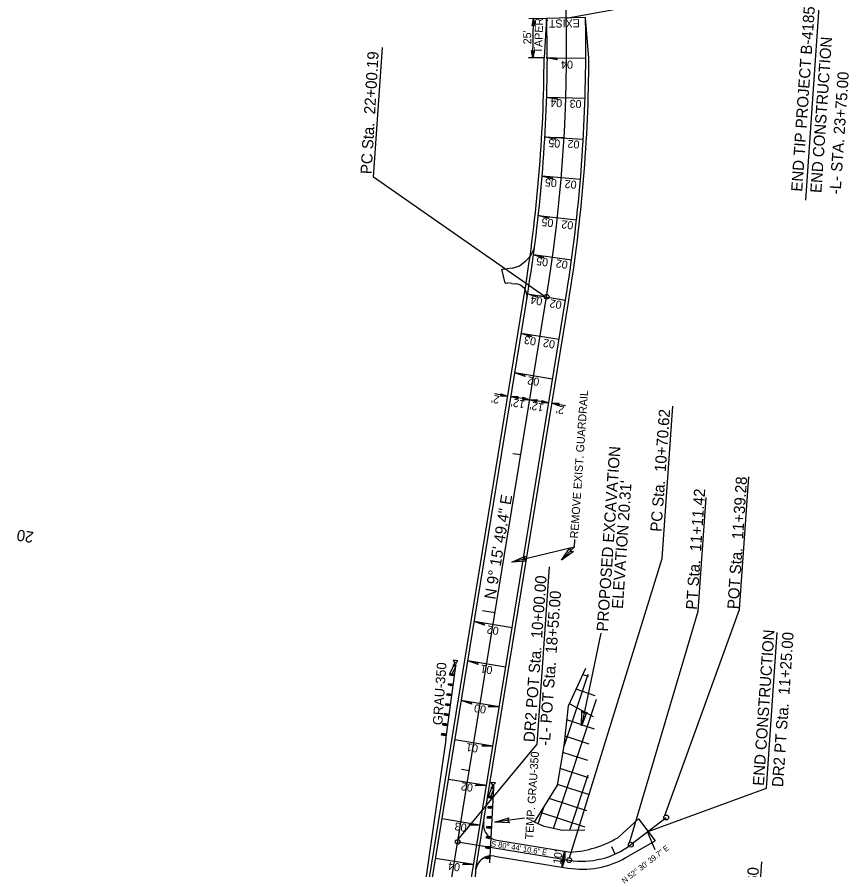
# Model space of a CAD drawing. Extents: x 2599146 to 2600072, y 728518 to 730269.
# Drawn here: x 2599189 to 2599709, y 729444 to 729977 of the extents above; entities that cross this region are included whole.
import ezdxf

# ---------------------------------------------------------------- set-up
doc = ezdxf.new("R2010")
doc.units = 0
for name, color, linetype in [('Default', 7, 'Continuous'), ('Old_Level_11', 7, 'Continuous'), ('Prop Dimension', 7, 'Continuous'), ('Prop Dimension Text', 7, 'Continuous'), ('Prop EOT', 7, 'Continuous'), ('Prop Guardrail', 7, 'Continuous'), ('Prop Guardrail Anchor Unit CELL', 7, 'Continuous'), ('Prop Horizontal Alignment', 7, 'Continuous'), ('Prop Horizontal Alignment Direction Label', 7, 'Continuous'), ('Prop Horizontal Alignment Station Label', 7, 'Continuous'), ('Prop Horizontal Alignment Tick Label', 7, 'Continuous'), ('Prop Horizontal Alignment Tick Large', 7, 'Continuous'), ('Prop Horizontal Alignment Tick Small', 7, 'Continuous'), ('Prop Structure Anchor Unit CELL', 7, 'Continuous'), ('Prop Superelevation Label', 7, 'Continuous'), ('Prop Terminator CELL', 7, 'Continuous')]:
    doc.layers.add(name, color=color, linetype=linetype)

msp = doc.modelspace()

# ---------------------------------------------------------------- linework, layer by layer
at = {"layer": 'Default'}
for p, q in [((2599533.53, 729546.45), (2599544.51, 729569.99)), ((2599530.82, 729521.23), (2599545.79, 729566.24)), ((2599546.3, 729564.75), (2599542.64, 729565.97)), ((2599550.35, 729552.86), (2599538.38, 729556.85)), ((2599524.29, 729469.93), (2599551.12, 729550.6)), ((2599530.85, 729521.55), (2599533.53, 729546.45)), ((2599549.26, 729539.63), (2599534.12, 729547.72)), ((2599549.77, 729531.98), (2599532.59, 729537.69)), ((2599546.48, 729522.54), (2599531.49, 729527.52)), ((2599526.68, 729496.9), (2599530.85, 729521.55)), ((2599545.59, 729512.29), (2599530.15, 729517.43)), ((2599546.01, 729501.62), (2599528.47, 729507.45)), ((2599534.44, 729468.74), (2599545.94, 729503.33)), ((2599546.06, 729491.06), (2599526.78, 729497.47)), ((2599512.38, 729473.9), (2599526.68, 729496.9)), ((2599545.05, 729480.86), (2599521.56, 729488.67)), ((2599514.73, 729472.85), (2599518.17, 729483.22)), ((2599544.04, 729470.65), (2599516.13, 729479.94)), ((2599518.38, 729471.2), (2599512.38, 729473.9)), ((2599529.83, 729468.73), (2599518.38, 729471.2)), ((2599543.86, 729468.77), (2599529.83, 729468.73))]:
    msp.add_line(p, q, dxfattribs=at)
at = {"layer": 'Old_Level_11'}
for p, q in [((2599537.43, 729650.36), (2599537.1, 729645.57)), ((2599537.1, 729645.57), (2599498.09, 729636.32)), ((2599537.1, 729645.57), (2599529.2, 729637.61)), ((2599506.12, 729476.4), (2599487.56, 729473.78))]:
    msp.add_line(p, q, dxfattribs=at)
at = {"layer": 'Prop Dimension'}
for p, q in [((2599519.89, 729976.04), (2599508.84, 729975.8)), ((2599511.21, 729951.4), (2599511.82, 729975.86)), ((2599518.37, 729951.37), (2599508.62, 729951.41)), ((2599495.61, 729740.06), (2599487.35, 729741.41)), ((2599509.42, 729737.81), (2599497.58, 729739.74)), ((2599521.27, 729735.87), (2599509.42, 729737.81)), ((2599523.24, 729735.55), (2599531.62, 729734.19)), ((2599553.75, 729591.98), (2599541.68, 729534.03)), ((2599531.22, 729455.63), (2599529.7, 729445.75))]:
    msp.add_line(p, q, dxfattribs=at)
at = {"layer": 'Prop EOT'}
for p, q in [((2599519.89, 729976.04), (2599518.37, 729951.37)), ((2599544.24, 729976.56), (2599519.89, 729976.04)), ((2599546.37, 729951.23), (2599544.24, 729976.56)), ((2599503.02, 729821.41), (2599507.16, 729824.81)), ((2599491.99, 729819.4), (2599495.13, 729819.64)), ((2599494.05, 729810.66), (2599491.99, 729819.4)), ((2599498.59, 729819.9), (2599495.13, 729819.64)), ((2599498.59, 729819.9), (2599503.02, 729821.41)), ((2599494.05, 729810.66), (2599495.53, 729810.73)), ((2599498.25, 729810.48), (2599495.53, 729810.73)), ((2599498.25, 729810.48), (2599500.4, 729810.29)), ((2599436.03, 729373.71), (2599506.1, 729804.42)), ((2599442.46, 729401.82), (2599508.08, 729804.09)), ((2599466.15, 729397.96), (2599531.76, 729800.23)), ((2599475.76, 729444.42), (2599533.74, 729799.91)), ((2599577.26, 729475.92), (2599564.34, 729464.11)), ((2599577.26, 729475.92), (2599587.77, 729462.23)), ((2599488.84, 729462.55), (2599534.86, 729455.04)), ((2599569.45, 729451.73), (2599587.77, 729462.23)), ((2599487.24, 729452.68), (2599533.25, 729445.17)), ((2599473.64, 729394.15), (2599475.76, 729444.42))]:
    msp.add_line(p, q, dxfattribs=at)
for centre, radius, start, end in [((2598577.46, 729945.59), 942.92, 0.35045, 1.85034), ((2598577.35, 729959.07), 967.05, 359.53612, 1.03601), ((2598577.38, 729955.9), 941, 350.73628, 359.72421), ((2598577.38, 729955.9), 943, 350.73628, 359.72421), ((2598577.38, 729955.9), 967, 350.73628, 359.72421), ((2598577.38, 729955.9), 969, 350.73628, 359.72421), ((2599497.65, 729836.41), 15, 309.3389, 352.6025), ((2599499.68, 729802.32), 8, 350.7363, 84.8302), ((2599490.45, 729472.42), 10, 170.7363, 260.7363), ((2599530.27, 729522.43), 67.55, 273.897, 300.2904), ((2599485.63, 729442.81), 10, 80.7363, 170.7363), ((2599542.1, 729499.45), 55, 260.7363, 299.81)]:
    msp.add_arc(centre, radius, start, end, dxfattribs=at)
at = {"layer": 'Prop Guardrail'}
msp.add_line((2599456.82, 729525.22), (2599435.02, 729373.01), dxfattribs=at)
at = {"layer": 'Prop Guardrail Anchor Unit CELL'}
for p, q in [((2599464.51, 729574.62), (2599461.61, 729575.07)), ((2599461.61, 729575.07), (2599462.27, 729573.78)), ((2599461.68, 729571.24), (2599461.81, 729572.23)), ((2599463.3, 729572.02), (2599461.68, 729571.24)), ((2599461.68, 729571.24), (2599461.75, 729571.73)), ((2599463.3, 729572.02), (2599461.81, 729572.23)), ((2599461.81, 729572.23), (2599463.16, 729571.03)), ((2599462.27, 729573.78), (2599461.95, 729571.76)), ((2599461.95, 729571.76), (2599462.56, 729571.66)), ((2599462.56, 729571.66), (2599463.16, 729571.57)), ((2599463.16, 729571.57), (2599463.48, 729573.59)), ((2599463.48, 729573.59), (2599464.51, 729574.62)), ((2599456.82, 729525.22), (2599463.23, 729571.52)), ((2599459.32, 729565.6), (2599459.46, 729566.6)), ((2599460.97, 729566.39), (2599459.32, 729565.6)), ((2599459.46, 729566.6), (2599461.68, 729571.24)), ((2599462.49, 729566.17), (2599459.46, 729566.6)), ((2599459.46, 729566.6), (2599460.84, 729565.39)), ((2599460.84, 729565.39), (2599460.97, 729566.39)), ((2599460.97, 729566.39), (2599463.16, 729571.03)), ((2599462.35, 729565.18), (2599460.97, 729566.39)), ((2599463.16, 729571.03), (2599461.68, 729571.24)), ((2599462.35, 729565.18), (2599459.32, 729565.6)), ((2599460.84, 729565.39), (2599462.49, 729566.17)), ((2599458.52, 729559.35), (2599458.66, 729560.34)), ((2599460.14, 729560.14), (2599458.52, 729559.35)), ((2599461.49, 729558.94), (2599458.52, 729559.35)), ((2599461.63, 729559.93), (2599458.66, 729560.34)), ((2599458.66, 729560.34), (2599460, 729559.15)), ((2599460, 729559.15), (2599460.14, 729560.14)), ((2599460, 729559.15), (2599461.63, 729559.93)), ((2599461.49, 729558.94), (2599460.14, 729560.14)), ((2599457.52, 729553.13), (2599457.66, 729554.12)), ((2599459.21, 729553.91), (2599457.52, 729553.13)), ((2599460.63, 729552.7), (2599457.52, 729553.13)), ((2599460.76, 729553.69), (2599457.66, 729554.12)), ((2599457.66, 729554.12), (2599459.07, 729552.92)), ((2599459.07, 729552.92), (2599459.21, 729553.91)), ((2599459.07, 729552.92), (2599460.76, 729553.69)), ((2599460.63, 729552.7), (2599459.21, 729553.91)), ((2599456.76, 729546.87), (2599456.89, 729547.87)), ((2599458.4, 729547.66), (2599456.76, 729546.87)), ((2599459.76, 729546.46), (2599456.76, 729546.87)), ((2599459.9, 729547.45), (2599456.89, 729547.87)), ((2599456.89, 729547.87), (2599458.26, 729546.67)), ((2599458.26, 729546.67), (2599458.4, 729547.66)), ((2599458.26, 729546.67), (2599459.9, 729547.45)), ((2599459.76, 729546.46), (2599458.4, 729547.66)), ((2599459.76, 729546.46), (2599459.9, 729547.45)), ((2599455.88, 729540.63), (2599456.02, 729541.63)), ((2599457.53, 729541.42), (2599455.88, 729540.63)), ((2599458.9, 729540.22), (2599455.88, 729540.63)), ((2599459.04, 729541.21), (2599456.02, 729541.63)), ((2599456.02, 729541.63), (2599457.39, 729540.43)), ((2599457.39, 729540.43), (2599457.53, 729541.42)), ((2599457.39, 729540.43), (2599459.04, 729541.21)), ((2599458.9, 729540.22), (2599457.53, 729541.42)), ((2599455.01, 729534.39), (2599455.15, 729535.38)), ((2599456.66, 729535.18), (2599455.01, 729534.39)), ((2599458.03, 729533.98), (2599455.01, 729534.39)), ((2599458.17, 729534.97), (2599455.15, 729535.38)), ((2599455.15, 729535.38), (2599456.52, 729534.19)), ((2599456.52, 729534.19), (2599456.66, 729535.18)), ((2599456.52, 729534.19), (2599458.17, 729534.97)), ((2599458.03, 729533.98), (2599456.66, 729535.18)), ((2599454.2, 729528.14), (2599454.34, 729529.14)), ((2599457.31, 729528.72), (2599454.34, 729529.14)), ((2599454.34, 729529.14), (2599455.68, 729527.94)), ((2599455.82, 729528.93), (2599454.2, 729528.14)), ((2599457.17, 729527.73), (2599454.2, 729528.14)), ((2599455.68, 729527.94), (2599455.82, 729528.93)), ((2599455.68, 729527.94), (2599457.31, 729528.72)), ((2599457.31, 729528.72), (2599455.82, 729528.93)), ((2599455.82, 729528.93), (2599457.17, 729527.73)), ((2599457.17, 729527.73), (2599457.31, 729528.72)), ((2599487.96, 729498.39), (2599485.02, 729498.6)), ((2599485.02, 729498.6), (2599485.79, 729497.36)), ((2599485.79, 729497.36), (2599485.65, 729495.32)), ((2599486.87, 729495.23), (2599487.01, 729497.28)), ((2599487.01, 729497.28), (2599487.96, 729498.39)), ((2599483.6, 729489.96), (2599485.42, 729494.78)), ((2599484.5, 729448.51), (2599486.94, 729495.2)), ((2599485.13, 729489.88), (2599486.92, 729494.7)), ((2599485.42, 729494.78), (2599485.47, 729495.78)), ((2599486.97, 729495.7), (2599485.42, 729494.78)), ((2599485.42, 729494.78), (2599485.44, 729495.28)), ((2599486.92, 729494.7), (2599485.42, 729494.78)), ((2599486.97, 729495.7), (2599485.47, 729495.78)), ((2599485.47, 729495.78), (2599486.92, 729494.7)), ((2599485.65, 729495.32), (2599486.26, 729495.28)), ((2599486.26, 729495.28), (2599486.87, 729495.23)), ((2599483.55, 729488.97), (2599483.6, 729489.96)), ((2599485.13, 729489.88), (2599483.55, 729488.97)), ((2599486.61, 729488.81), (2599483.55, 729488.97)), ((2599486.66, 729489.8), (2599483.6, 729489.96)), ((2599483.6, 729489.96), (2599485.08, 729488.89)), ((2599485.08, 729488.89), (2599485.13, 729489.88)), ((2599485.08, 729488.89), (2599486.66, 729489.8)), ((2599486.61, 729488.81), (2599485.13, 729489.88)), ((2599483.28, 729482.67), (2599483.34, 729483.67)), ((2599484.83, 729483.59), (2599483.28, 729482.67)), ((2599486.28, 729482.51), (2599483.28, 729482.67)), ((2599486.33, 729483.51), (2599483.34, 729483.67)), ((2599483.34, 729483.67), (2599484.78, 729482.59)), ((2599484.78, 729482.59), (2599484.83, 729483.59)), ((2599484.78, 729482.59), (2599486.33, 729483.51)), ((2599486.28, 729482.51), (2599484.83, 729483.59)), ((2599482.81, 729476.38), (2599482.87, 729477.38)), ((2599484.43, 729477.3), (2599482.81, 729476.38)), ((2599485.95, 729476.22), (2599482.81, 729476.38)), ((2599486, 729477.22), (2599482.87, 729477.38)), ((2599482.87, 729477.38), (2599484.38, 729476.3)), ((2599484.38, 729476.3), (2599484.43, 729477.3)), ((2599484.38, 729476.3), (2599486, 729477.22)), ((2599485.95, 729476.22), (2599484.43, 729477.3)), ((2599482.59, 729470.09), (2599482.64, 729471.08)), ((2599484.15, 729471.01), (2599482.59, 729470.09)), ((2599485.67, 729470.93), (2599482.64, 729471.08)), ((2599482.64, 729471.08), (2599484.1, 729470.01)), ((2599484.1, 729470.01), (2599484.15, 729471.01)), ((2599484.1, 729470.01), (2599485.67, 729470.93)), ((2599485.62, 729469.93), (2599484.15, 729471.01)), ((2599485.62, 729469.93), (2599485.67, 729470.93)), ((2599485.62, 729469.93), (2599482.59, 729470.09)), ((2599482.25, 729463.79), (2599482.3, 729464.79)), ((2599483.82, 729464.71), (2599482.25, 729463.79)), ((2599485.29, 729463.63), (2599482.25, 729463.79)), ((2599485.34, 729464.63), (2599482.3, 729464.79)), ((2599482.3, 729464.79), (2599483.77, 729463.72)), ((2599483.77, 729463.72), (2599483.82, 729464.71)), ((2599483.77, 729463.72), (2599485.34, 729464.63)), ((2599485.29, 729463.63), (2599483.82, 729464.71)), ((2599481.91, 729457.5), (2599481.96, 729458.5)), ((2599483.49, 729458.42), (2599481.91, 729457.5)), ((2599484.96, 729457.34), (2599481.91, 729457.5)), ((2599485.01, 729458.34), (2599481.96, 729458.5)), ((2599481.96, 729458.5), (2599483.43, 729457.42)), ((2599483.43, 729457.42), (2599483.49, 729458.42)), ((2599483.43, 729457.42), (2599485.01, 729458.34)), ((2599484.96, 729457.34), (2599483.49, 729458.42)), ((2599481.63, 729451.21), (2599481.69, 729452.21)), ((2599483.18, 729452.13), (2599481.63, 729451.21)), ((2599484.63, 729451.05), (2599481.63, 729451.21)), ((2599484.68, 729452.05), (2599481.69, 729452.21)), ((2599481.69, 729452.21), (2599483.13, 729451.13)), ((2599483.13, 729451.13), (2599483.18, 729452.13)), ((2599483.13, 729451.13), (2599484.68, 729452.05)), ((2599484.68, 729452.05), (2599483.18, 729452.13)), ((2599483.18, 729452.13), (2599484.63, 729451.05)), ((2599484.63, 729451.05), (2599484.68, 729452.05))]:
    msp.add_line(p, q, dxfattribs=at)
at = {"layer": 'Prop Horizontal Alignment'}
for p, q in [((2599454.31, 729399.89), (2599519.92, 729802.16)), ((2599572.53, 729459.78), (2599594.64, 729476.73)), ((2599464.35, 729461.47), (2599534.06, 729450.11))]:
    msp.add_line(p, q, dxfattribs=at)
for centre, radius, start, end in [((2598577.38, 729955.9), 955, 350.73628, 19.06961), ((2599542.1, 729499.45), 50, 260.7363, 307.489)]:
    msp.add_arc(centre, radius, start, end, dxfattribs=at)
at = {"layer": 'Prop Horizontal Alignment Station Label'}
for p, q in [((2599532.16, 729976.3), (2599691.61, 730005.27)), ((2599691.61, 730005.27), (2599681.78, 729862.54)), ((2599411.7, 729876.89), (2599417.28, 729957.78)), ((2599518.44, 729802.4), (2599411.7, 729876.89)), ((2599592.15, 729638.65), (2599598.72, 729733.71)), ((2599640.55, 729606.66), (2599646.29, 729689.68)), ((2599614.69, 729605.66), (2599619.6, 729676.7)), ((2599534.3, 729451.59), (2599592.15, 729638.65)), ((2599513.99, 729522.53), (2599521.64, 729633.4)), ((2599571.62, 729460.97), (2599614.69, 729605.66)), ((2599593.73, 729477.92), (2599640.55, 729606.66)), ((2599657.32, 729494.98), (2599664.04, 729592.32)), ((2599464.59, 729462.95), (2599513.99, 729522.53)), ((2599583.31, 729468.04), (2599657.32, 729494.98)), ((2599587.79, 729456.47), (2599582.9, 729467.73)), ((2599648.85, 729368.16), (2599654.43, 729449.02))]:
    msp.add_line(p, q, dxfattribs=at)
for centre in [(2599519.92, 729802.16), (2599594.64, 729476.73), (2599464.35, 729461.47), (2599572.53, 729459.78), (2599534.06, 729450.11)]:
    msp.add_circle(centre, 1.5, dxfattribs=at)
at = {"layer": 'Prop Horizontal Alignment Tick Large'}
for p, q in [((2599487.7, 729604.58), (2599479.8, 729605.87)), ((2599464.35, 729461.47), (2599465.64, 729469.37))]:
    msp.add_line(p, q, dxfattribs=at)
at = {"layer": 'Prop Horizontal Alignment Tick Small'}
for p, q in [((2599530.82, 729901.33), (2599525.82, 729901.62)), ((2599519.89, 729801.97), (2599514.96, 729802.78)), ((2599503.79, 729703.28), (2599498.86, 729704.08)), ((2599471.6, 729505.89), (2599466.66, 729506.69)), ((2599562.76, 729453.92), (2599560.69, 729458.47))]:
    msp.add_line(p, q, dxfattribs=at)
at = {"layer": 'Prop Superelevation Label'}
for p, q in [((2599519.69, 729951.36), (2599544.05, 729951.24)), ((2599543.91, 729925.93), (2599519.92, 729926.68)), ((2599518.84, 729902.02), (2599542.8, 729900.64)), ((2599541.02, 729875.39), (2599517.1, 729877.39)), ((2599514.73, 729852.82), (2599538.58, 729850.2)), ((2599535.49, 729825.07), (2599511.71, 729828.32)), ((2599508.05, 729803.91), (2599531.73, 729800.04)), ((2599527.71, 729775.37), (2599504.02, 729779.23)), ((2599523.69, 729750.69), (2599500, 729754.56)), ((2599498.35, 729595.35), (2599474.66, 729599.21)), ((2599494.32, 729570.68), (2599470.64, 729574.54)), ((2599490.3, 729546), (2599466.61, 729549.87)), ((2599486.27, 729521.33), (2599462.59, 729525.19)), ((2599482.25, 729496.65), (2599458.56, 729500.52)), ((2599478.23, 729471.98), (2599454.54, 729475.84)), ((2599474.2, 729447.31), (2599450.51, 729451.17))]:
    msp.add_line(p, q, dxfattribs=at)
at = {"layer": 'Prop Terminator CELL'}
for points in [[(2599510.94, 729971.39), (2599511.82, 729975.86), (2599512.51, 729971.32), (2599511.72, 729971.92)], [(2599512.09, 729955.88), (2599511.21, 729951.4), (2599510.52, 729955.95), (2599511.31, 729955.35)], [(2599526.43, 729950.17), (2599519.69, 729951.36), (2599525.62, 729951.33)], [(2599526.63, 729925.31), (2599519.92, 729926.68), (2599525.85, 729926.49)], [(2599525.51, 729900.47), (2599518.84, 729902.02), (2599524.75, 729901.68)], [(2599523.73, 729875.67), (2599517.1, 729877.39), (2599523.01, 729876.9)], [(2599521.31, 729850.93), (2599514.73, 729852.82), (2599520.62, 729852.17)], [(2599518.24, 729826.26), (2599511.71, 729828.32), (2599517.58, 729827.52)], [(2599514.52, 729801.67), (2599508.05, 729803.91), (2599513.9, 729802.95)], [(2599510.5, 729777), (2599504.02, 729779.23), (2599509.87, 729778.28)], [(2599506.47, 729752.32), (2599500, 729754.56), (2599505.85, 729753.6)], [(2599491.29, 729741.55), (2599495.61, 729740.06), (2599491.01, 729740), (2599491.71, 729740.7)], [(2599501.9, 729738.25), (2599497.58, 729739.74), (2599502.18, 729739.8), (2599501.48, 729739.1)], [(2599505.11, 729739.3), (2599509.42, 729737.81), (2599504.83, 729737.74), (2599505.53, 729738.44)], [(2599513.74, 729736.32), (2599509.42, 729737.81), (2599514.02, 729737.87), (2599513.32, 729737.17)], [(2599516.95, 729737.36), (2599521.27, 729735.87), (2599516.67, 729735.81), (2599517.37, 729736.51)], [(2599527.56, 729734.06), (2599523.24, 729735.55), (2599527.84, 729735.61), (2599527.14, 729734.92)], [(2599536.64, 729642.91), (2599529.2, 729637.61), (2599534.44, 729645.16), (2599534.76, 729643.22)], [(2599507.21, 729636.89), (2599498.09, 729636.32), (2599506.53, 729639.96), (2599505.78, 729638.14)], [(2599481.14, 729596.98), (2599474.66, 729599.21), (2599480.51, 729598.26)], [(2599477.11, 729572.31), (2599470.64, 729574.54), (2599476.48, 729573.59)], [(2599473.09, 729547.63), (2599466.61, 729549.87), (2599472.46, 729548.91)], [(2599490.3, 729546), (2599483.41, 729545.91), (2599484.45, 729546.96)], [(2599545.04, 729542.53), (2599541.68, 729534.03), (2599541.96, 729543.22), (2599543.29, 729541.77)], [(2599486.27, 729521.33), (2599479.38, 729521.24), (2599480.43, 729522.28)], [(2599482.25, 729496.65), (2599475.36, 729496.56), (2599476.4, 729497.61)], [(2599496.69, 729473.5), (2599487.56, 729473.78), (2599496.3, 729476.63), (2599495.38, 729474.89)], [(2599478.23, 729471.98), (2599471.33, 729471.89), (2599472.38, 729472.93)], [(2599529.77, 729451.3), (2599531.22, 729455.63), (2599531.32, 729451.04), (2599530.62, 729451.73)], [(2599531.15, 729450.08), (2599529.7, 729445.75), (2599529.6, 729450.34), (2599530.3, 729449.65)], [(2599474.2, 729447.31), (2599467.31, 729447.21), (2599468.35, 729448.26)]]:
    msp.add_lwpolyline(points, close=True, dxfattribs=at)

# ---------------------------------------------------------------- texts
at = {"layer": 'Default'}
for s, p in [('PROPOSED EXCAVATION', (2599558.12, 729592.8)), ("ELEVATION 20.31'", (2599567.57, 729606.96))]:
    msp.add_text(s, height=7, rotation=86.0601, dxfattribs=at).set_placement(p)
at = {"layer": 'Old_Level_11'}
for s, p in [('REMOVE EXIST. GUARDRAIL', (2599539.52, 729650.99)), ('TEMP. GRAU-350', (2599511.39, 729462.94))]:
    msp.add_text(s, height=5, rotation=86.05, dxfattribs=at).set_placement(p)
at = {"layer": 'Prop Dimension Text'}
for s, rotation, p in [('TAPER', 88.1393, (2599517.06, 729954.06)), ("25'", 90.5476, (2599510.34, 729959.9)), ("2'", 170.0119, (2599490.75, 729740.08)), ("12'", 170.0119, (2599506.73, 729737.12)), ("12'", 170.0119, (2599518.42, 729735.16)), ("2'", 170.0119, (2599531.3, 729733.45)), ("10'", 81.5422, (2599528.76, 729447.32))]:
    msp.add_text(s, height=5, rotation=rotation, dxfattribs=at).set_placement(p)
at = {"layer": 'Prop Horizontal Alignment Direction Label'}
for s, height, rotation, p in [('N 9%%d 15\' 49.4" E', 7, 80.7363, (2599487.82, 729612.68)), ('S 80%%d 44\' 10.6" E', 3.5, 350.7363, (2599485.01, 729458.75)), ('N 52%%d 30\' 39.7" E', 3.5, 37.489, (2599568.52, 729435.31))]:
    msp.add_text(s, height=height, rotation=rotation, dxfattribs=at).set_placement(p)
at = {"layer": 'Prop Horizontal Alignment Station Label'}
for s, rotation, p in [('END TIP PROJECT B-4185', 86.0601, (2599679.67, 729867.64)), ('END CONSTRUCTION', 86.0601, (2599691.64, 729866.81)), ('PC Sta.  22+00.19', 86.6566, (2599410.52, 729878.6)), ('-L- STA. 23+75.00', 86.0601, (2599703.61, 729865.99)), ('PC Sta.  10+70.62', 85.9033, (2599591.66, 729655.1)), ('POT Sta.  11+39.28', 86.2224, (2599639.8, 729606.75)), ('PT Sta.  11+11.42', 86.0569, (2599613.9, 729606.42)), ('DR2 POT Sta.  10+00.00', 85.8246, (2599512.38, 729523.65)), ('-L- POT Sta.  18+55.00', 85.8246, (2599521.94, 729521.43)), ('END CONSTRUCTION', 86.0569, (2599655.7, 729496.4)), ('DR2 PT Sta.  11+25.00', 86.0569, (2599667.68, 729495.57)), ('PT Sta.  17+92.60', 86.2323, (2599647.66, 729369.95))]:
    msp.add_text(s, height=7, rotation=rotation, dxfattribs=at).set_placement(p)
at = {"layer": 'Prop Horizontal Alignment Tick Label'}
msp.add_text('20', height=7, rotation=170.7363, dxfattribs=at).set_placement((2599199.69, 729655.1))
at = {"layer": 'Prop Structure Anchor Unit CELL'}
msp.add_text('GRAU-350', height=6, rotation=86.0601, dxfattribs=at).set_placement((2599454.69, 729534.32))
at = {"layer": 'Prop Superelevation Label'}
for s, rotation, p in [('EXIST.', 180.9116, (2599540.67, 729975.56)), ('04', 179.698, (2599536.39, 729949.63)), ('04', 177.6328, (2599529.75, 729925.52)), ('03', 177.0022, (2599541.86, 729924.93)), ('05', 176.8179, (2599528.57, 729900.26)), ('02', 176.7528, (2599540.59, 729899.72)), ('05', 174.6478, (2599526.5, 729875.5)), ('02', 175.647, (2599538.83, 729874.55)), ('05', 173.7483, (2599524.41, 729850.54)), ('02', 173.5005, (2599536.85, 729849.11)), ('05', 171.5889, (2599521.17, 729825.9)), ('02', 171.7783, (2599533.43, 729824.45)), ('04', 170.6077, (2599517.61, 729801.5)), ('02', 170.7139, (2599529.66, 729799.34)), ('03', 169.7917, (2599513.72, 729776.44)), ('02', 170.5935, (2599525.49, 729774.64)), ('02', 170.869, (2599515.66, 729751.26)), ('02', 171.1283, (2599490.32, 729595.65)), ('01', 171.1283, (2599486.41, 729571.17)), ('00', 171.1283, (2599482.39, 729546.5)), ('01', 171.1283, (2599477.4, 729522.13)), ('02', 171.1283, (2599474.17, 729497.64)), ('03', 171.1283, (2599470.24, 729472.68)), ('04', 171.1283, (2599466.13, 729447.9))]:
    msp.add_text(s, height=5, rotation=rotation, dxfattribs=at).set_placement(p)

doc.saveas('drawing.dxf')
